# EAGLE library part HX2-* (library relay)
Compact & Slim 2 Form C Non-polarized Relay NAiS Source: http://www.mew-europe.com/.. en_ds_61011_0000.pdf
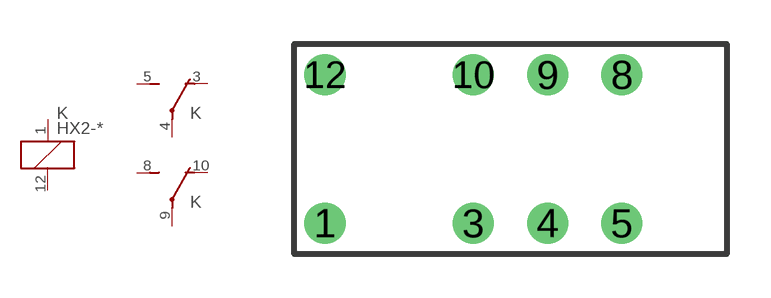
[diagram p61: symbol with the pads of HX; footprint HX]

Designator prefix K; gates 1=K 2=U 3=U

## HX2-1.5V (OC_FARNELL: unknown; OC_NEWARK: unknown), HX2-3V (OC_FARNELL: unknown; OC_NEWARK: unknown), HX2-4.5V (OC_FARNELL: unknown; OC_NEWARK: unknown), HX2-5V (OC_FARNELL: unknown; OC_NEWARK: unknown), HX2-6V (OC_FARNELL: unknown; OC_NEWARK: unknown), HX2-9V (OC_FARNELL: unknown; OC_NEWARK: unknown), HX2-12V (OC_FARNELL: unknown; OC_NEWARK: unknown), HX2-24V (OC_FARNELL: unknown; OC_NEWARK: unknown)  [HX]
1  1:1  pas
3  2:O  pas
4  2:P  pas
5  2:S  pas
8  3:S  pas
9  3:P  pas
10  3:O  pas
12  1:2  pas

## Footprint HX (pad centres in mm)
Compact & Slim 2 Form C Non-polarized Relay NAiS Source: http://www.mew-europe.com/.. en_ds_61011_0000.pdf
drill 0.9 round: 1 -6.35,-2.54; 3 -1.27,-2.54; 4 1.27,-2.54; 5 3.81,-2.54; 8 3.81,2.54; 9 1.27,2.54; 10 -1.27,2.54; 12 -6.35,2.54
